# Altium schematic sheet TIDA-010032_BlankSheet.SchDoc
size 431 x 279 mm; Date: Not shown in title block; ApprovedBy: Not shown in title block; CheckedBy: Not shown in title block; Author: Not shown in title block; CompanyName: Not shown in title block; Engineer: Not shown in title block; Organization: Not shown in title block; Address1: Not shown in title block; Address2: Not shown in title block; Address3: Not shown in title block; Address4: Not shown in title block; DocumentNumber: 1; Revision: Use project parameter SCH_Rev; SheetNumber: 2; SheetTotal: 3; PageSetup: Record=PageOptions¦CenterHorizontal=True¦CenterVertical=True¦PrintScale=1.00¦XCorrection=1.00¦YCorrection=1.00¦PrintKind=0¦BorderSize=5000000¦LeftOffset=0¦BottomOffset=0¦Orientation=2¦PaperLength=1000¦PaperWidth=1000¦Scale=100¦PaperSource=15¦PrintQuality=-3¦MediaType=1¦DitherType=10¦PrintScaleMode=1¦PaperKind=Letter¦PaperIndex=1
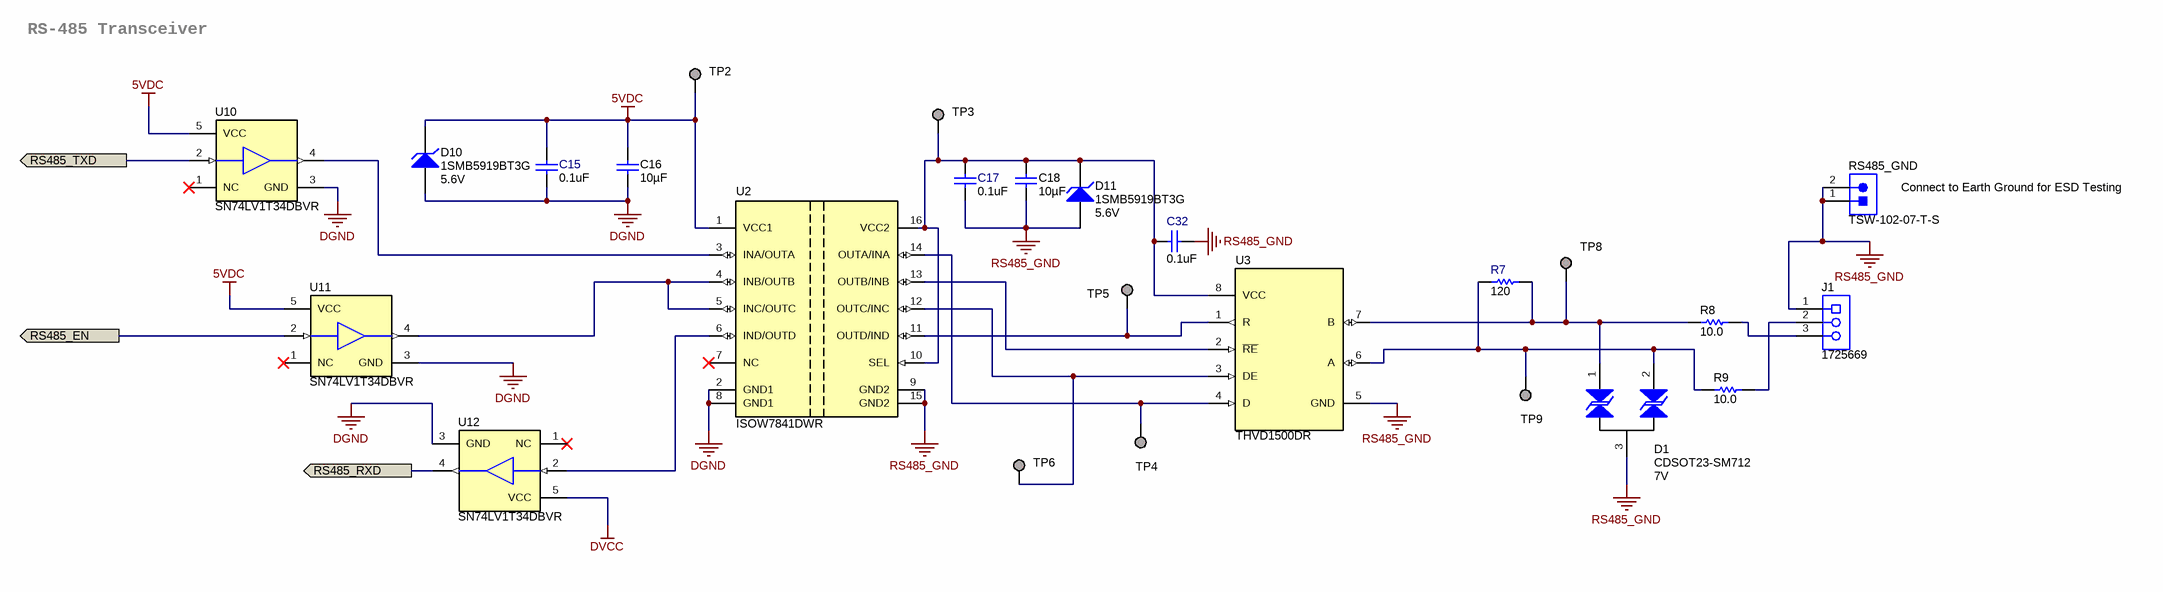
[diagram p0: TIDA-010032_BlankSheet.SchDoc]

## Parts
C15  value 0.1uF  [0603]  (hidden comment: C0603C104J4RACTU)
C16  ValueDisplayed: 10µF  [0603]  (hidden comment: C0603C106M9PACTU)
C17  value 0.1uF  [0603]  (hidden comment: C0603C104J4RACTU)
C18  ValueDisplayed: 10µF  [0603]  (hidden comment: C0603C106M9PACTU)
C32  value 0.1uF  [0603]  (hidden comment: C0603C104J4RACTU)
D1  CDSOT23-SM712  value 7V  [SOT-23]
D10  1SMB5919BT3G  value 5.6V  [SMB]
D11  1SMB5919BT3G  value 5.6V  [SMB]
J1  1725669  [Phoenix_1725669]
R7  value 120  [0603]  (hidden comment: CRCW0603120RJNEA)
R8  ValueDisplayed: 10.0  [2512]  (hidden comment: CRCW251210R0FKEG)
R9  ValueDisplayed: 10.0  [2512]  (hidden comment: CRCW251210R0FKEG)
RS485_GND  TSW-102-07-T-S  [Samtec_TSW-102-07-T-S]
TP2  TESTPOINT  [TESTPOINT]  (value not drawn)  (no BOM)
TP3  TESTPOINT  [TESTPOINT]  (value not drawn)  (no BOM)
TP4  TESTPOINT  [TESTPOINT]  (value not drawn)  (no BOM)
TP5  TESTPOINT  [TESTPOINT]  (value not drawn)  (no BOM)
TP6  TESTPOINT  [TESTPOINT]  (value not drawn)  (no BOM)
TP8  TESTPOINT  [TESTPOINT]  (value not drawn)  (no BOM)
TP9  TESTPOINT  [TESTPOINT]  (value not drawn)  (no BOM)
U2  ISOW7841DWR  [DW0016B_N]
U3  THVD1500DR  [D0008A_N]
U10  SN74LV1T34DBVR  [DBV0005A_N]
U11  SN74LV1T34DBVR  [DBV0005A_N]
U12  SN74LV1T34DBVR  [DBV0005A_N]

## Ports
RS485_EN, RS485_RXD, RS485_TXD

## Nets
5VDC: C15.1 C16.2 D10.1(K) TP2.1 U2.1(VCC1) U10.5(VCC) U11.5(VCC)
DGND: C15.2 C16.1 D10.2(A) U2.2(GND1) U2.8(GND1) U10.3(GND) U11.3(GND) U12.3(GND)
DVCC: U12.5(VCC)
RS485_GND: C17.2 C18.1 C32.2 D1.3 D11.2(A) J1.1 RS485_GND.1 RS485_GND.2 U2.9(GND2) U2.15(GND2) U3.5(GND)
RS485_EN: U11.2(A) ; port RS485_EN
RS485_RXD: U12.4(Y) ; port RS485_RXD
RS485_TXD: U10.2(A) ; port RS485_TXD
NetC17_1: C17.1 C18.2 C32.1 D11.1(K) TP3.1 U2.10(SEL) U2.16(VCC2) U3.8(VCC)
NetD1_1: D1.1 R7.1 R8.1 TP8.1 U3.7(B)
NetD1_2: D1.2 R7.2 R9.1 TP9.1 U3.6(A)
NetJ1_2: J1.2 R9.2
NetJ1_3: J1.3 R8.2
NetTP4_1: TP4.1 U2.14(OUTA/INA) U3.4(D)
NetTP5_1: TP5.1 U2.11(OUTD/IND) U3.1(R)
NetTP6_1: TP6.1 U2.12(OUTC/INC) U3.3(DE)
NetU2_3: U2.3(INA/OUTA) U10.4(Y)
NetU2_4: U2.4(INB/OUTB) U2.5(INC/OUTC) U11.4(Y)
NetU2_6: U2.6(IND/OUTD) U12.2(A)
NetU2_13: U2.13(OUTB/INB) U3.2(~{RE})

Not connected (* = marked no-connect by the designer): U2 7(NC)*; U10 1(NC)*; U11 1(NC)*; U12 1(NC)*

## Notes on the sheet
- RS-485 Transceiver
- (near RS485_GND) Connect to Earth Ground for ESD Testing

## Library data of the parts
C15 C17 C32 = C0603C104J4RACTU: CAP, CERM, 0.1uF, 16V, +/-5%, X7R, 0603; Manufacturer: Kemet; Polarized: N; CompType: Capacitor; ValueDisplayed: 0.1µF; U/M: EA; Cap_F: 0.0000001; Tolerance_%: 5; Value1: Unknown; VDC_V: 16; TaMin_C: -55; TaMax_C: 125
C16 C18 = C0603C106M9PACTU: CAP, CERM, 10 µF, 6.3 V, +/- 20%, X5R, 0603; Manufacturer: Kemet; Polarized: N; CompType: Capacitor; Value: 10uF; U/M: EA; Cap_F: 0.00001; Tolerance_%: 20; ESR_ohm: 0.004; Value1: 0.004 ohm; VDC_V: 6.3; Value2: 6.3V; IRMS_A: 8.9; TaMin_C: -55; TaMax_C: 85; SizeArea_mm2: 1.28; SizeAreaWB_mm2: 4.68; SizeX_mm: 1.6; SizeY_mm: 0.8; SizeZ_mm: 1; AEC Category: Q200
D1 = CDSOT23-SM712: Diode, TVS, Bi, 7 V, SOT-23; Manufacturer: Bourns; SymbolCreator: a0411947; U/M: EA; Vr_V: 7; Value1: W; SizeAreaWB_mm2: 14; SizeArea_mm2: 7.5; SizeX_mm: 2.5; SizeY_mm: 3; SizeZ_mm: 1.1; AEC Category: Q101
D10 D11 = 1SMB5919BT3G: Diode, Zener, 5.6 V, 550 mW, SMB; Manufacturer: ON Semiconductor; SymbolCreator: a0412235; U/M: EA; Power_W: 0.55; Vz_V: 5.6; Value1: 0.55W; RJA_CperW: 226; SizeAreaWB_mm2: 44.156; SizeArea_mm2: 21.336; SizeY_mm: 3.81; SizeZ_mm: 2.6; AEC Category: Q101
J1 = 1725669: Terminal Block, 3x1, 2.54 mm, TH; Manufacturer: Phoenix Contact; SymbolCreator: a0412235
R7 = CRCW0603120RJNEA: RES, 120 ohm, 5%, 0.1W, 0603; Manufacturer: Vishay-Dale; CompType: Resistor; Value_Code: 120R; Tolerance_%: 5; Power_W: 0.1; VDC_V: 75; TempCo: 200 ppm/C; EIA_Code: E24; U/M: EA
R8 R9 = CRCW251210R0FKEG: RES, 10.0, 1%, 1 W, AEC-Q200 Grade 0, 2512; Manufacturer: Vishay-Dale; CompType: Resistor; Value: 10.0; Res_ohm: 10; Value_Code: 10R0; Tolerance_%: 1; Value2: 1W; VDC_V: 500; TempCo: 100 ppm/C; SizeArea_mm2: 20.16; SizeX_mm: 6.3; SizeY_mm: 3.2; SizeZ_mm: 0.71; EIA_Code: E96; U/M: EA; AEC Category: Q200; AEC Qualified: Y; AEC Grade: 0
RS485_GND = TSW-102-07-T-S: Header, 2.54 mm, 2x1, Tin, TH; Manufacturer: Samtec; SymbolCreator: a0412235; Pitch_mm: 2.54; Gender: Male; Shrouded: N; Row_Count: 1; Current_A: 6.3; Voltage_V: 550; Cert_CSA: Y
TP2-TP6 TP8 TP9 = TESTPOINT: TEST POINT.  No entry in BOM.
U2 = ISOW7841DWR: ISOW7841DW, DW0016B (SOIC-16); Manufacturer: Texas Instruments; SymbolCreator: a0411947; SizeArea_mm2: 107.12; SizeAreaWB_mm2: 152.52; SizeX_mm: 10.4; SizeY_mm: 10.3; SizeZ_mm: 2.65; CompType: IC; U/M: EA
U3 = THVD1500DR: 250 kbps RS-485 Transceivers With ±12-kV IEC ESD Protection, D0008A (SOIC-8); Manufacturer: Texas Instruments; SymbolCreator: a0411947; SizeArea_mm2: 30.38; SizeAreaWB_mm2: 56.58; SizeX_mm: 4.9; SizeY_mm: 6.2; SizeZ_mm: 1.75; CompType: IC; U/M: EA
U10-U12 = SN74LV1T34DBVR: Single Power Supply BUFFER Logic Level Shifter (no enable), DBV0005A (SOT-5); Manufacturer: Texas Instruments; SymbolCreator: Altium; SizeArea_mm2: 8.12; SizeAreaWB_mm2: 14.82; SizeX_mm: 2.8; SizeY_mm: 2.9; SizeZ_mm: 1.45; CompType: IC; U/M: EA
